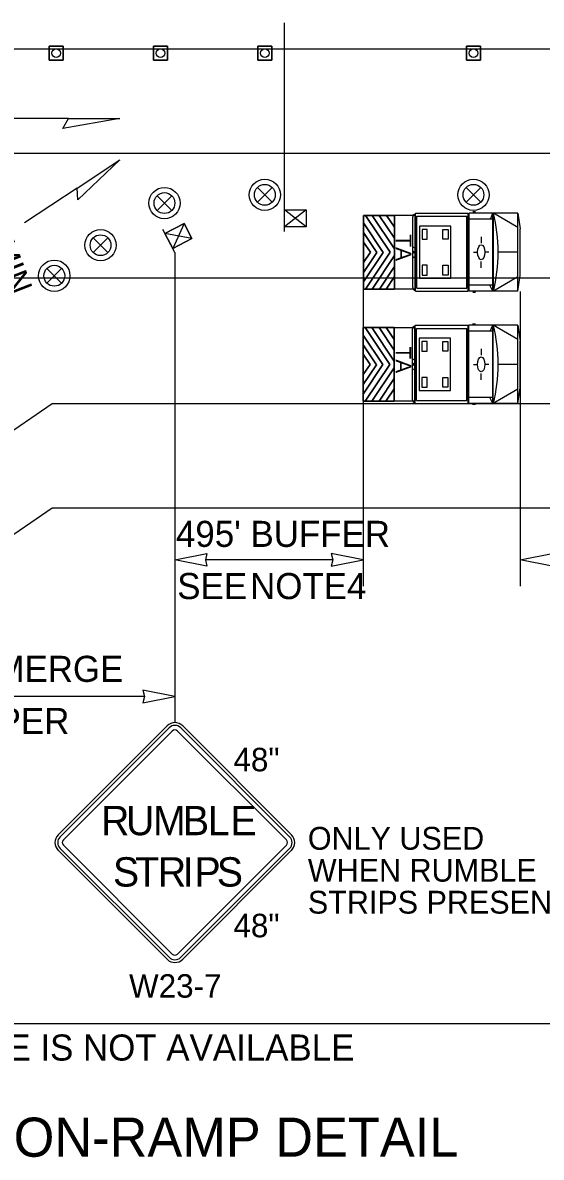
# Model space of a CAD drawing. Extents: x 99999 to 100116, y 99995 to 100013.
# Drawn here: x 100052.647 to 100054.238, y 100004.799 to 100008.279 of the extents above; entities that cross this region are included whole.
import ezdxf

# ---------------------------------------------------------------- set-up
doc = ezdxf.new("R2010")
doc.units = 0
for name, color, linetype in [('RD_MK_LineEdgeYellow', 7, 'Continuous'), ('RD_MK_LineLane', 7, 'Continuous'), ('SH_DE_DetailHeading2Text', 7, 'Continuous'), ('TR_SN_ConstructionSigns', 7, 'Continuous'), ('TR_WZ_PortableSignMount5ftMinBlk-Org', 7, 'Continuous'), ('TR_WZ_PortableSignMount5ftMinBlk-Wht', 7, 'Continuous'), ('TR_WZ_TrafficCone', 7, 'Continuous'), ('TR_WZ_TrafficSafetyDrum', 7, 'Continuous'), ('TR_WZ_TransportableAttenuator', 7, 'Continuous'), ('TR_WZ_WorkZoneDetails', 7, 'Continuous'), ('TR_WZ_WorkZoneTextCurrent', 7, 'Continuous')]:
    doc.layers.add(name, color=color, linetype=linetype)

msp = doc.modelspace()

# ---------------------------------------------------------------- linework, layer by layer
at = {"layer": 'RD_MK_LineEdgeYellow'}
for p, q in [((100048.195, 100007.8789), (100055.43, 100007.8789)), ((100052.1758, 100006.7269), (100052.7368, 100007.1109)), ((100052.7368, 100007.1109), (100055.43, 100007.1109))]:
    msp.add_line(p, q, dxfattribs=at)
at = {"layer": 'RD_MK_LineLane'}
msp.add_lwpolyline([(100055.43, 100007.4949), (100048.195, 100007.4949)], dxfattribs=at)
at = {"layer": 'TR_SN_ConstructionSigns'}
for p, q in [((100053.0896, 100006.122), (100052.7555, 100005.7879)), ((100053.4715, 100005.7879), (100053.1374, 100006.122)), ((100053.0956, 100006.1161), (100052.7615, 100005.7819)), ((100052.7714, 100005.772), (100053.1055, 100006.1061)), ((100053.1215, 100006.1061), (100053.4556, 100005.772)), ((100053.4655, 100005.7819), (100053.1314, 100006.1161)), ((100052.7555, 100005.7402), (100053.0896, 100005.4061)), ((100052.7615, 100005.7462), (100053.0956, 100005.412)), ((100053.1055, 100005.422), (100052.7714, 100005.7561)), ((100053.4556, 100005.7561), (100053.1215, 100005.422)), ((100053.1314, 100005.412), (100053.4655, 100005.7462)), ((100053.1374, 100005.4061), (100053.4715, 100005.7402))]:
    msp.add_line(p, q, dxfattribs=at)
for centre, radius, start, end in [((100053.1135, 100006.0982), 0.0338, 45, 135), ((100053.1135, 100006.0982), 0.0253, 45, 135), ((100053.1135, 100006.0982), 0.0113, 45, 135), ((100052.7794, 100005.764), 0.0338, 135, 225), ((100052.7794, 100005.764), 0.0253, 135, 225), ((100052.7794, 100005.764), 0.0113, 135, 225), ((100053.4476, 100005.764), 0.0113, 315, 45), ((100053.4476, 100005.764), 0.0253, 315, 45), ((100053.4476, 100005.764), 0.0338, 315, 45), ((100053.1135, 100005.4299), 0.0338, 225, 315), ((100053.1135, 100005.4299), 0.0253, 225, 315), ((100053.1135, 100005.4299), 0.0113, 225, 315)]:
    msp.add_arc(centre, radius, start, end, dxfattribs=at)
at = {"layer": 'TR_WZ_PortableSignMount5ftMinBlk-Org'}
for p, q in [((100053.1417, 100007.663), (100053.107, 100007.5859)), ((100053.1135, 100007.5735), (100053.0761, 100007.6443)), ((100053.166, 100007.617), (100053.0827, 100007.6319)), ((100053.1243, 100007.6245), (100053.1243, 100007.6245)), ((100053.1244, 100007.6246), (100053.1244, 100007.6246))]:
    msp.add_line(p, q, dxfattribs=at)
for points in [[(100053.1417, 100007.663), (100053.166, 100007.617), (100053.107, 100007.5859), (100053.0827, 100007.6319)], [(100053.107, 100007.5859), (100053.166, 100007.617), (100053.1417, 100007.663), (100053.0827, 100007.6319)]]:
    msp.add_lwpolyline(points, close=True, dxfattribs=at)
at = {"layer": 'TR_WZ_PortableSignMount5ftMinBlk-Wht'}
for p, q in [((100053.45, 100007.6389), (100053.45, 100007.7189)), ((100053.5167, 100007.7049), (100053.45, 100007.6529)), ((100053.5167, 100007.6529), (100053.45, 100007.7049)), ((100053.4834, 100007.6789), (100053.4834, 100007.6789)), ((100053.4835, 100007.679), (100053.4835, 100007.679))]:
    msp.add_line(p, q, dxfattribs=at)
msp.add_lwpolyline([(100053.5167, 100007.7049), (100053.5167, 100007.6529), (100053.45, 100007.6529), (100053.45, 100007.7049)], close=True, dxfattribs=at)
at = {"layer": 'TR_WZ_TrafficCone'}
for points in [[(100052.7281, 100008.2069), (100052.7707, 100008.2069), (100052.7707, 100008.1642), (100052.7281, 100008.1642), (100052.7281, 100008.2069)], [(100052.7281, 100008.1642), (100052.7707, 100008.1642), (100052.7707, 100008.2069), (100052.7281, 100008.2069), (100052.7281, 100008.1642)], [(100053.0481, 100008.2069), (100053.0907, 100008.2069), (100053.0907, 100008.1642), (100053.0481, 100008.1642), (100053.0481, 100008.2069)], [(100053.0481, 100008.1642), (100053.0907, 100008.1642), (100053.0907, 100008.2069), (100053.0481, 100008.2069), (100053.0481, 100008.1642)], [(100053.3681, 100008.2069), (100053.4107, 100008.2069), (100053.4107, 100008.1642), (100053.3681, 100008.1642), (100053.3681, 100008.2069)], [(100053.3681, 100008.1642), (100053.4107, 100008.1642), (100053.4107, 100008.2069), (100053.3681, 100008.2069), (100053.3681, 100008.1642)], [(100054.0081, 100008.2069), (100054.0507, 100008.2069), (100054.0507, 100008.1642), (100054.0081, 100008.1642), (100054.0081, 100008.2069)], [(100054.0081, 100008.1642), (100054.0507, 100008.1642), (100054.0507, 100008.2069), (100054.0081, 100008.2069), (100054.0081, 100008.1642)]]:
    msp.add_lwpolyline(points, dxfattribs=at)
for centre in [(100052.7494, 100008.1856), (100053.0694, 100008.1856), (100053.3894, 100008.1856), (100054.0294, 100008.1856)]:
    msp.add_circle(centre, 0.0133, dxfattribs=at)
at = {"layer": 'TR_WZ_TrafficSafetyDrum'}
for p, q in [((100053.3668, 100007.7735), (100053.412, 100007.7283)), ((100053.412, 100007.7735), (100053.3668, 100007.7283)), ((100054.0068, 100007.7735), (100054.052, 100007.7283)), ((100054.052, 100007.7735), (100054.0068, 100007.7283)), ((100053.0589, 100007.7483), (100053.1042, 100007.703)), ((100053.1042, 100007.7483), (100053.0589, 100007.703)), ((100052.8628, 100007.6189), (100052.9081, 100007.5736)), ((100052.9081, 100007.6189), (100052.8628, 100007.5736)), ((100052.721, 100007.5253), (100052.7662, 100007.48)), ((100052.7662, 100007.5253), (100052.721, 100007.48))]:
    msp.add_line(p, q, dxfattribs=at)
for centre, radius in [((100053.3894, 100007.7509), 0.048), ((100053.3894, 100007.7509), 0.048), ((100054.0294, 100007.7509), 0.048), ((100054.0294, 100007.7509), 0.048), ((100053.0815, 100007.7256), 0.048), ((100053.0815, 100007.7256), 0.048), ((100053.0815, 100007.7256), 0.032), ((100053.3894, 100007.7509), 0.032), ((100054.0294, 100007.7509), 0.032), ((100052.8855, 100007.5963), 0.048), ((100052.8855, 100007.5963), 0.048), ((100052.8855, 100007.5963), 0.032), ((100052.7436, 100007.5027), 0.048), ((100052.7436, 100007.5027), 0.048), ((100052.7436, 100007.5027), 0.032)]:
    msp.add_circle(centre, radius, dxfattribs=at)
at = {"layer": 'TR_WZ_TransportableAttenuator'}
for p, q in [((100053.7186, 100007.6875), (100053.6986, 100007.6875)), ((100053.6986, 100007.6875), (100053.7735, 100007.5747)), ((100053.7735, 100007.5747), (100053.6986, 100007.6875)), ((100053.6986, 100007.6875), (100053.7186, 100007.6875)), ((100053.7868, 100007.5848), (100053.7186, 100007.6875)), ((100053.7186, 100007.6875), (100053.7868, 100007.5848)), ((100053.7622, 100007.6875), (100053.7406, 100007.6875)), ((100053.7406, 100007.6875), (100053.7868, 100007.618)), ((100053.7868, 100007.618), (100053.7406, 100007.6875)), ((100053.7406, 100007.6875), (100053.7622, 100007.6875)), ((100053.7868, 100007.6512), (100053.7622, 100007.6875)), ((100053.7622, 100007.6875), (100053.7868, 100007.6512)), ((100053.8512, 100007.6873), (100053.7868, 100007.6873)), ((100053.7868, 100007.6873), (100053.7868, 100007.462)), ((100053.8471, 100007.691), (100053.8506, 100007.691)), ((100053.8506, 100007.4589), (100053.8506, 100007.691)), ((100053.8512, 100007.6949), (100054.0137, 100007.6949)), ((100053.8512, 100007.4549), (100053.8512, 100007.6949)), ((100053.8512, 100007.4624), (100053.8512, 100007.6873)), ((100053.8558, 100007.4645), (100053.8558, 100007.6853)), ((100053.8558, 100007.6853), (100054.0091, 100007.6853)), ((100054.0091, 100007.4645), (100054.0091, 100007.6853)), ((100054.0137, 100007.4549), (100054.0137, 100007.6949)), ((100054.0159, 100007.4549), (100054.0159, 100007.6949)), ((100054.1651, 100007.6949), (100054.0159, 100007.6949)), ((100054.0362, 100007.6983), (100054.0273, 100007.6983)), ((100054.0813, 100007.6763), (100054.0891, 100007.6949)), ((100054.0891, 100007.4549), (100054.0891, 100007.6949)), ((100054.0905, 100007.4549), (100054.0905, 100007.6949)), ((100054.1651, 100007.651), (100054.0905, 100007.6949)), ((100054.1651, 100007.4549), (100054.1651, 100007.6949)), ((100054.1651, 100007.6949), (100054.1724, 100007.6465)), ((100053.7525, 100007.574), (100053.6924, 100007.6646)), ((100053.6924, 100007.6646), (100053.6924, 100007.6351)), ((100053.6924, 100007.6351), (100053.6924, 100007.6646)), ((100053.6924, 100007.6646), (100053.7525, 100007.574)), ((100053.7868, 100007.618), (100053.7868, 100007.6512)), ((100053.7868, 100007.6512), (100053.7868, 100007.618)), ((100053.8436, 100007.4662), (100053.8436, 100007.6837)), ((100054.0891, 100007.6763), (100054.0159, 100007.6763)), ((100053.6924, 100007.6351), (100053.7332, 100007.5737)), ((100053.7332, 100007.5737), (100053.6924, 100007.6351)), ((100054.0533, 100007.6225), (100054.0533, 100007.6031)), ((100054.1724, 100007.5034), (100054.1724, 100007.6465)), ((100053.7133, 100007.5746), (100053.6924, 100007.606)), ((100053.6924, 100007.606), (100053.6924, 100007.5435)), ((100053.6924, 100007.606), (100053.7133, 100007.5746)), ((100053.6924, 100007.5435), (100053.6924, 100007.606)), ((100053.7868, 100007.5648), (100053.7868, 100007.5848)), ((100053.7868, 100007.5848), (100053.7868, 100007.5648)), ((100053.8436, 100007.5918), (100053.8506, 100007.5873)), ((100053.6924, 100007.5435), (100053.7133, 100007.5746)), ((100053.7133, 100007.5746), (100053.6924, 100007.5435)), ((100053.6924, 100007.4835), (100053.7525, 100007.574)), ((100053.7525, 100007.574), (100053.6924, 100007.4835)), ((100053.7332, 100007.5737), (100053.6924, 100007.5126)), ((100053.6924, 100007.5126), (100053.7332, 100007.5737)), ((100053.7735, 100007.5747), (100053.6986, 100007.462)), ((100053.6986, 100007.462), (100053.7735, 100007.5747)), ((100053.719, 100007.462), (100053.7868, 100007.5648)), ((100053.7868, 100007.5648), (100053.719, 100007.462)), ((100053.8436, 100007.558), (100053.8506, 100007.5625)), ((100053.8455, 100007.5749), (100053.8487, 100007.5749)), ((100053.8471, 100007.5716), (100053.8471, 100007.5783)), ((100054.0295, 100007.5748), (100054.0394, 100007.5748)), ((100054.0422, 100007.5753), (100054.0422, 100007.5753)), ((100054.0533, 100007.5274), (100054.0533, 100007.5468)), ((100054.0771, 100007.5748), (100054.0672, 100007.5748)), ((100054.1651, 100007.5749), (100054.1051, 100007.5749)), ((100053.6924, 100007.5126), (100053.6924, 100007.4835)), ((100053.6924, 100007.4835), (100053.6924, 100007.5126)), ((100053.7868, 100007.5315), (100053.7412, 100007.462)), ((100053.7412, 100007.462), (100053.7868, 100007.5315)), ((100053.7868, 100007.5002), (100053.7868, 100007.5315)), ((100053.7868, 100007.5315), (100053.7868, 100007.5002)), ((100053.7615, 100007.462), (100053.7868, 100007.5002)), ((100053.7868, 100007.5002), (100053.7615, 100007.462)), ((100054.1651, 100007.4989), (100054.0905, 100007.4549)), ((100054.1651, 100007.4549), (100054.1724, 100007.5034)), ((100053.6986, 100007.462), (100053.719, 100007.462)), ((100053.719, 100007.462), (100053.6986, 100007.462)), ((100053.7412, 100007.462), (100053.7615, 100007.462)), ((100053.7615, 100007.462), (100053.7412, 100007.462)), ((100053.8512, 100007.462), (100053.7868, 100007.462)), ((100053.8471, 100007.4589), (100053.8506, 100007.4589)), ((100053.8512, 100007.4549), (100054.0137, 100007.4549)), ((100053.8558, 100007.4645), (100054.0091, 100007.4645)), ((100054.0891, 100007.4735), (100054.0159, 100007.4735)), ((100054.1651, 100007.4549), (100054.0159, 100007.4549)), ((100054.0362, 100007.4515), (100054.0273, 100007.4515)), ((100054.0891, 100007.4549), (100054.0796, 100007.4735)), ((100053.7177, 100007.3435), (100053.6976, 100007.3435)), ((100053.6976, 100007.3435), (100053.7727, 100007.2307)), ((100053.7727, 100007.2307), (100053.6976, 100007.3435)), ((100053.6976, 100007.3435), (100053.7177, 100007.3435)), ((100053.786, 100007.2408), (100053.7177, 100007.3435)), ((100053.7177, 100007.3435), (100053.786, 100007.2408)), ((100053.7614, 100007.3435), (100053.7398, 100007.3435)), ((100053.7398, 100007.3435), (100053.786, 100007.274)), ((100053.786, 100007.274), (100053.7398, 100007.3435)), ((100053.7398, 100007.3435), (100053.7614, 100007.3435)), ((100053.786, 100007.3071), (100053.7614, 100007.3435)), ((100053.7614, 100007.3435), (100053.786, 100007.3071)), ((100053.8505, 100007.3433), (100053.786, 100007.3433)), ((100053.786, 100007.3433), (100053.786, 100007.118)), ((100053.8429, 100007.1221), (100053.8429, 100007.3396)), ((100053.8464, 100007.347), (100053.85, 100007.347)), ((100053.85, 100007.1148), (100053.85, 100007.347)), ((100053.8505, 100007.3509), (100054.0134, 100007.3509)), ((100053.8505, 100007.1109), (100053.8505, 100007.3509)), ((100053.8505, 100007.1184), (100053.8505, 100007.3433)), ((100053.8551, 100007.1205), (100053.8551, 100007.3413)), ((100053.8551, 100007.3413), (100054.0088, 100007.3413)), ((100054.0088, 100007.1205), (100054.0088, 100007.3413)), ((100054.0134, 100007.1109), (100054.0134, 100007.3509)), ((100054.0156, 100007.1109), (100054.0156, 100007.3509)), ((100054.1651, 100007.3509), (100054.0156, 100007.3509)), ((100054.0359, 100007.3543), (100054.027, 100007.3543)), ((100054.0811, 100007.3323), (100054.089, 100007.3509)), ((100054.089, 100007.1109), (100054.089, 100007.3509)), ((100054.0903, 100007.1109), (100054.0903, 100007.3509)), ((100054.1651, 100007.307), (100054.0903, 100007.3509)), ((100054.1651, 100007.1109), (100054.1651, 100007.3509)), ((100054.1651, 100007.3509), (100054.1724, 100007.3024)), ((100053.7517, 100007.23), (100053.6914, 100007.3205)), ((100053.6914, 100007.3205), (100053.6914, 100007.2911)), ((100053.6914, 100007.2911), (100053.6914, 100007.3205)), ((100053.6914, 100007.3205), (100053.7517, 100007.23)), ((100053.786, 100007.274), (100053.786, 100007.3071)), ((100053.786, 100007.3071), (100053.786, 100007.274)), ((100054.089, 100007.3323), (100054.0156, 100007.3323)), ((100054.1724, 100007.1593), (100054.1724, 100007.3024)), ((100053.6914, 100007.2911), (100053.7323, 100007.2297)), ((100053.7323, 100007.2297), (100053.6914, 100007.2911)), ((100054.0531, 100007.2784), (100054.0531, 100007.2591)), ((100053.7124, 100007.2305), (100053.6914, 100007.2619)), ((100053.6914, 100007.2619), (100053.6914, 100007.1995)), ((100053.6914, 100007.2619), (100053.7124, 100007.2305)), ((100053.6914, 100007.1995), (100053.6914, 100007.2619)), ((100053.786, 100007.2207), (100053.786, 100007.2408)), ((100053.786, 100007.2408), (100053.786, 100007.2207)), ((100053.8429, 100007.2478), (100053.85, 100007.2433)), ((100053.8464, 100007.2275), (100053.8464, 100007.2343)), ((100053.6914, 100007.1995), (100053.7124, 100007.2305)), ((100053.7124, 100007.2305), (100053.6914, 100007.1995)), ((100053.6914, 100007.1394), (100053.7517, 100007.23)), ((100053.7517, 100007.23), (100053.6914, 100007.1394)), ((100053.7323, 100007.2297), (100053.6914, 100007.1686)), ((100053.6914, 100007.1686), (100053.7323, 100007.2297)), ((100053.7727, 100007.2307), (100053.6977, 100007.118)), ((100053.6977, 100007.118), (100053.7727, 100007.2307)), ((100053.7181, 100007.118), (100053.786, 100007.2207)), ((100053.786, 100007.2207), (100053.7181, 100007.118)), ((100053.8429, 100007.214), (100053.85, 100007.2185)), ((100053.8448, 100007.2309), (100053.8481, 100007.2309)), ((100054.0292, 100007.2307), (100054.0392, 100007.2308)), ((100054.0419, 100007.2313), (100054.0419, 100007.2313)), ((100054.0531, 100007.1833), (100054.0531, 100007.2027)), ((100054.0769, 100007.2307), (100054.067, 100007.2308)), ((100054.1651, 100007.2309), (100054.105, 100007.2309)), ((100053.6914, 100007.1686), (100053.6914, 100007.1394)), ((100053.6914, 100007.1394), (100053.6914, 100007.1686)), ((100053.786, 100007.1875), (100053.7403, 100007.118)), ((100053.7403, 100007.118), (100053.786, 100007.1875)), ((100053.786, 100007.1562), (100053.786, 100007.1875)), ((100053.786, 100007.1875), (100053.786, 100007.1562)), ((100053.7607, 100007.118), (100053.786, 100007.1562)), ((100053.786, 100007.1562), (100053.7607, 100007.118)), ((100054.089, 100007.1295), (100054.0156, 100007.1295)), ((100054.089, 100007.1109), (100054.0795, 100007.1295)), ((100054.1651, 100007.1549), (100054.0903, 100007.1109)), ((100054.1651, 100007.1109), (100054.1724, 100007.1593)), ((100053.6977, 100007.118), (100053.7181, 100007.118)), ((100053.7181, 100007.118), (100053.6977, 100007.118)), ((100053.7403, 100007.118), (100053.7607, 100007.118)), ((100053.7607, 100007.118), (100053.7403, 100007.118)), ((100053.8505, 100007.118), (100053.786, 100007.118)), ((100053.8464, 100007.1148), (100053.85, 100007.1148)), ((100053.8505, 100007.1109), (100054.0134, 100007.1109)), ((100053.8551, 100007.1205), (100054.0088, 100007.1205)), ((100054.1651, 100007.1109), (100054.0156, 100007.1109)), ((100054.0359, 100007.1075), (100054.027, 100007.1075))]:
    msp.add_line(p, q, dxfattribs=at)
for points in [[(100053.7868, 100007.6875), (100053.6924, 100007.6875), (100053.6924, 100007.462), (100053.7868, 100007.462)], [(100053.8638, 100007.4949), (100053.9598, 100007.4949), (100053.9598, 100007.6549), (100053.8638, 100007.6549)], [(100053.8718, 100007.6149), (100053.8878, 100007.6149), (100053.8878, 100007.6449), (100053.8718, 100007.6449)], [(100053.9518, 100007.6149), (100053.9358, 100007.6149), (100053.9358, 100007.6449), (100053.9518, 100007.6449)], [(100053.8718, 100007.5049), (100053.8878, 100007.5049), (100053.8878, 100007.5349), (100053.8718, 100007.5349)], [(100053.9518, 100007.5049), (100053.9358, 100007.5049), (100053.9358, 100007.5349), (100053.9518, 100007.5349)], [(100053.786, 100007.3435), (100053.6914, 100007.3435), (100053.6914, 100007.118), (100053.786, 100007.118)], [(100053.8632, 100007.1509), (100053.9594, 100007.1509), (100053.9594, 100007.3109), (100053.8632, 100007.3109)], [(100053.8712, 100007.2709), (100053.8872, 100007.2709), (100053.8872, 100007.3009), (100053.8712, 100007.3009)], [(100053.9513, 100007.2709), (100053.9353, 100007.2709), (100053.9353, 100007.3009), (100053.9513, 100007.3009)], [(100053.8712, 100007.1609), (100053.8872, 100007.1609), (100053.8872, 100007.1909), (100053.8712, 100007.1909)], [(100053.9513, 100007.1609), (100053.9353, 100007.1609), (100053.9353, 100007.1909), (100053.9513, 100007.1909)]]:
    msp.add_lwpolyline(points, close=True, dxfattribs=at)
for points in [[(100053.7868, 100007.462), (100053.6924, 100007.462), (100053.6924, 100007.6875), (100053.7868, 100007.6873)], [(100053.786, 100007.118), (100053.6914, 100007.118), (100053.6914, 100007.3435), (100053.786, 100007.3433)]]:
    msp.add_lwpolyline(points, dxfattribs=at)
for centre, major_axis, ratio, start_param, end_param in [((100053.8471, 100007.6837), (0, 0.00732), 0.481608, 0, 1.570796), ((100053.9838, 100007.5749), (0, 0.2519), 0.481608, 4.215667, 5.208926), ((100053.8471, 100007.4662), (0, -0.00732), 0.481608, 4.712389, 6.283185), ((100053.8464, 100007.3396), (0, 0.00732), 0.482618, 0, 1.570796), ((100053.9835, 100007.2309), (0, 0.2519), 0.482618, 4.215667, 5.208926), ((100053.8464, 100007.1222), (0, -0.00732), 0.482618, 4.712389, 6.283185)]:
    msp.add_ellipse(centre, major_axis=major_axis, ratio=ratio, start_param=start_param, end_param=end_param, dxfattribs=at)
for centre, major_axis, ratio in [((100054.0533, 100007.5749), (0, -0.0231), 0.481608), ((100053.8471, 100007.5749), (0, -0.00338), 0.481608), ((100053.8464, 100007.2309), (0, -0.00338), 0.482618), ((100054.0531, 100007.2309), (0, -0.0231), 0.482618)]:
    msp.add_ellipse(centre, major_axis=major_axis, ratio=ratio, dxfattribs=at)
at = {"layer": 'TR_WZ_WorkZoneDetails'}
for p, q in [((100053.45, 100007.7189), (100053.45, 100008.2789)), ((100053.45, 100007.7111), (100053.45, 100008.2769)), ((100048.195, 100008.1989), (100055.43, 100008.1989)), ((100052.7876, 100007.985), (100052.5947, 100007.985)), ((100052.8136, 100007.7713), (100052.6526, 100007.6651)), ((100053.1135, 100007.5735), (100053.1135, 100006.1319)), ((100053.6914, 100007.4607), (100053.6914, 100006.5509)), ((100054.1724, 100007.4548), (100054.1724, 100006.5509)), ((100052.1758, 100006.4069), (100052.7368, 100006.7909)), ((100052.7368, 100006.7909), (100055.43, 100006.7909)), ((100053.5977, 100006.6309), (100053.2072, 100006.6309)), ((100053.0198, 100006.2119), (100052.2056, 100006.2119)), ((100054.3691, 100005.2082), (100050.6962, 100005.2082))]:
    msp.add_line(p, q, dxfattribs=at)
for points in [[(100052.9448, 100007.985), (100052.7698, 100007.9541), (100052.7876, 100007.985)], [(100052.9448, 100007.8579), (100052.8157, 100007.7357), (100052.8136, 100007.7713)], [(100053.1135, 100006.6309), (100053.2118, 100006.6502), (100053.2072, 100006.6309), (100053.2118, 100006.6116)], [(100053.6914, 100006.6309), (100053.5931, 100006.6502), (100053.5977, 100006.6309), (100053.5931, 100006.6116)], [(100054.1724, 100006.6309), (100054.2707, 100006.6502), (100054.2662, 100006.6309), (100054.2707, 100006.6116)], [(100053.1135, 100006.2119), (100053.0152, 100006.2312), (100053.0198, 100006.2119), (100053.0152, 100006.1926)]]:
    msp.add_lwpolyline(points, close=True, dxfattribs=at)

# ---------------------------------------------------------------- texts
at = {"layer": 'SH_DE_DetailHeading2Text'}
msp.add_text('OPEN RIGHT PARALLEL ON-RAMP DETAIL', height=0.12, rotation=360, dxfattribs=at).set_placement((100050.7196, 100004.8003))
at = {"layer": 'TR_SN_ConstructionSigns'}
for s, p in [('48"', (100053.2933, 100005.9826)), ('48"', (100053.2933, 100005.4735)), ('W23-7', (100052.9729, 100005.2882))]:
    msp.add_text(s, height=0.072, rotation=360, dxfattribs=at).set_placement(p)
for s, p in [('R', (100052.8871, 100005.7865)), ('U', (100052.9636, 100005.7865)), ('M', (100053.0464, 100005.7865)), ('B', (100053.1382, 100005.7865)), ('L', (100053.2147, 100005.7865)), ('E', (100053.284, 100005.7865)), ('S', (100052.9236, 100005.629)), ('T', (100052.992, 100005.629)), ('R', (100053.0613, 100005.629)), ('I', (100053.1378, 100005.629)), ('P', (100053.1738, 100005.629)), ('S', (100053.2422, 100005.629))]:
    msp.add_text(s, height=0.09, dxfattribs=at).set_placement(p)
at = {"layer": 'TR_WZ_TransportableAttenuator'}
for height, p in [(0.048, (100053.7912, 100007.6298)), (0.0481, (100053.7904, 100007.2858))]:
    msp.add_text('TA', height=height, rotation=270, dxfattribs=at).set_placement(p)
at = {"layer": 'TR_WZ_WorkZoneDetails'}
for s, p in [('ONLY USED', (100053.5214, 100005.742)), ('WHEN RUMBLE', (100053.5214, 100005.644)), ('STRIPS PRESENT', (100053.5214, 100005.546))]:
    msp.add_text(s, height=0.07, dxfattribs=at).set_placement(p)
at = {"layer": 'TR_WZ_WorkZoneTextCurrent'}
msp.add_text("14' MIN", height=0.07, rotation=291.3231, dxfattribs=at).set_placement((100052.497, 100007.7371))
for s, p in [("495' BUFFER", (100053.1169, 100006.6709)), ('SEE', (100053.1208, 100006.5109)), ('NOTE', (100053.3443, 100006.5109)), ('4', (100053.6415, 100006.5109)), ("1160' MERGE", (100052.2749, 100006.2569)), ('TAPER', (100052.4332, 100006.0969)), ('CLOSE ON-RAMP IF DISTANCE IS NOT AVAILABLE', (100051.0782, 100005.0953))]:
    msp.add_text(s, height=0.08, dxfattribs=at).set_placement(p)

doc.saveas('drawing.dxf')
